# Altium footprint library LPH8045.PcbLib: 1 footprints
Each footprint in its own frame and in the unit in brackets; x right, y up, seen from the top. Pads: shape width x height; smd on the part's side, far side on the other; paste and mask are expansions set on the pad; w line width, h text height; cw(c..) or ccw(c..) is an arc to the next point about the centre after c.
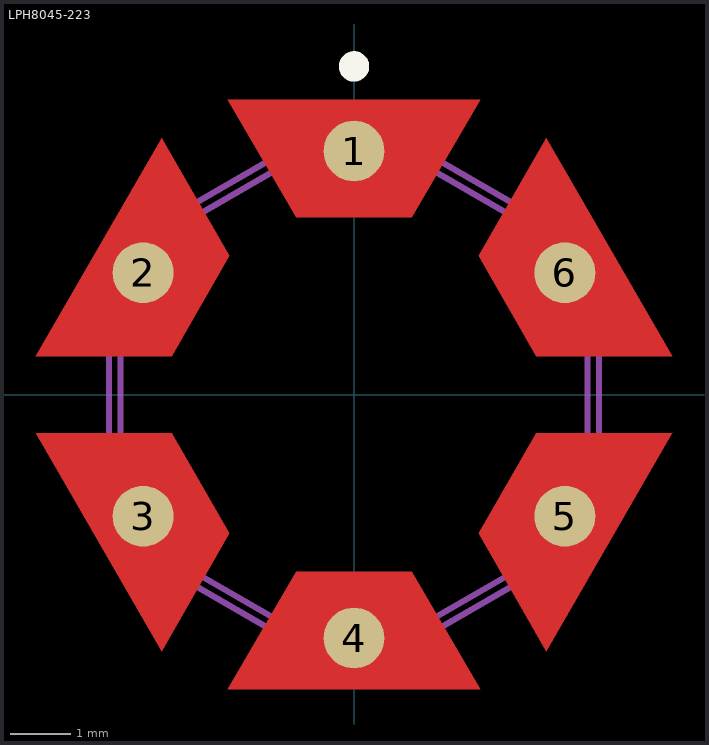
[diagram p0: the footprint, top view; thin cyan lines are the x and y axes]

## LPH8045-223 [mm] "SMD, 6-Leads, Body 8.76x8.05mm"
height 4.7
pads (6):
  round 1 smd: 1(0,4) 2(-3.464,2) 3(-3.464,-2) 4(0,-4) 5(3.464,-2) 6(3.464,2)
Top Layer:
  region: 2.045,2.278 3.157,4.213 5.227,0.627 2.995,0.632
  region: 2.995,-0.632 5.227,-0.627 3.157,-4.213 2.045,-2.278
  region: 0.95,-2.91 2.07,-4.84 -2.07,-4.84 -0.95,-2.91
  region: -2.045,-2.278 -3.157,-4.213 -5.227,-0.627 -2.995,-0.632
  region: -2.995,0.632 -5.227,0.627 -3.157,4.213 -2.045,2.278
  region: -0.95,2.91 -2.07,4.84 2.07,4.84 0.95,2.91
Top Overlay:
  circle w0.25: c0,5.39 r0.125
M5 Assembly Top:
  circle w0.1: c0,3.5 r0.3
  lines w0.1: -4.025,-1.788 -4.025,1.788 -3.561,2.592 -0.464,4.38 0.464,4.38 3.561,2.592 4.025,1.789 4.025,-1.788 3.561,-2.592 0.464,-4.38 -0.464,-4.38 -3.561,-2.592 -4.025,-1.788 ; -3.837,-1.754 -3.437,-2.446 -0.4,-4.2 0.4,-4.2 3.437,-2.446 3.837,-1.754 3.837,1.754 3.437,2.446 0.4,4.2 -0.4,4.2 -3.437,2.446 -3.837,1.754 -3.837,-1.754
  text ".Designator" at -1.524,-0.508 h1.02
3D body: height 4.7, standoff 4.69, extent -3.838,-4.201 3.838,4.201
3D body: height 4.69, standoff 0, extent -4.026,-4.381 4.026,4.381
3D body: height 4.71, standoff 0, extent -0.305,3.195 0.305,3.805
